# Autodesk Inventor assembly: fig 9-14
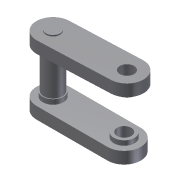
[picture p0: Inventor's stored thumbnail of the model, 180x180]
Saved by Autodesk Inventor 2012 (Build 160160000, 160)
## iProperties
Shininess: 64.0
Length Units: 11269
Angle Units: 11279
Time Units: 11290
Mass Units: 11283
Length Display Precision: 3
Angle Display Precision: 2
Created: 2002-01
Part Number: fig 9-14
Document SubType Name: Assembly
Designer: ***
Density: 0.0
Volumn: 0.0
Area: 0.0
PropertySet Name: Model Information
Control State: 0
Master: False
Checked Out: False
Author: ***
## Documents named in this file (3)
- C:\Users\CadCim\Documents\SAILESH\inventor-2011-fact-prt\c09_inv_2011-prt\c09_inv_2012_prt\fig 9-14.iam
- C:\Users\CadCim\Documents\SAILESH\inventor-2011-fact-prt\c09_inv_2011-prt\c09_inv_2012_prt\Part5.ipt
- C:\Users\CadCim\Documents\SAILESH\inventor-2011-fact-prt\c09_inv_2011-prt\c09_inv_2012_prt\Part6.ipt
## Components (3 placed, 2 different names)
1. Part5:1 — Insert:1
2. Part6:1 — Insert:1, Insert:2
3. Part5:2 — Insert:2
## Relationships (2: Insert 2)
- Insert:1: Part5:1 ↔ Part6:1
- Insert:2: Part6:1 ↔ Part5:2
